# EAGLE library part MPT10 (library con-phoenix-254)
PHOENIX CONNECTOR
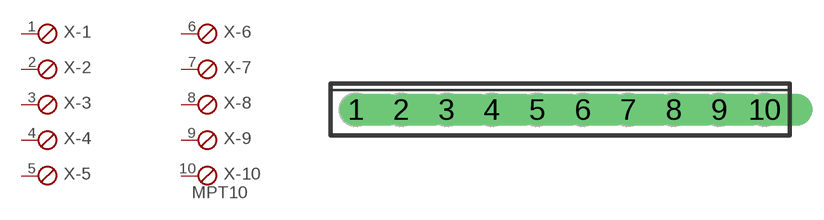
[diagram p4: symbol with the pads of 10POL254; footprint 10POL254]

Designator prefix X; gates -1=SKB -2=SKB -3=SKB -4=SKB -5=SKB -6=SKB -7=SKB -8=SKB -9=SKB -10=SKBV

## MPT10  [10POL254]
1  -1:1  pas
2  -2:1  pas
3  -3:1  pas
4  -4:1  pas
5  -5:1  pas
6  -6:1  pas
7  -7:1  pas
8  -8:1  pas
9  -9:1  pas
10  -10:1  pas

## Footprint 10POL254 (pad centres in mm)
PHOENIX CONNECTOR
drill 1.2 offset: 1 -11.43,0; 2 -8.89,0; 3 -6.35,0; 4 -3.81,0; 5 -1.27,0; 6 1.27,0; 7 3.81,0; 8 6.35,0; 9 8.89,0; 10 11.43,0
